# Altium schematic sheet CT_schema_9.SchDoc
size 274 x 160 mm
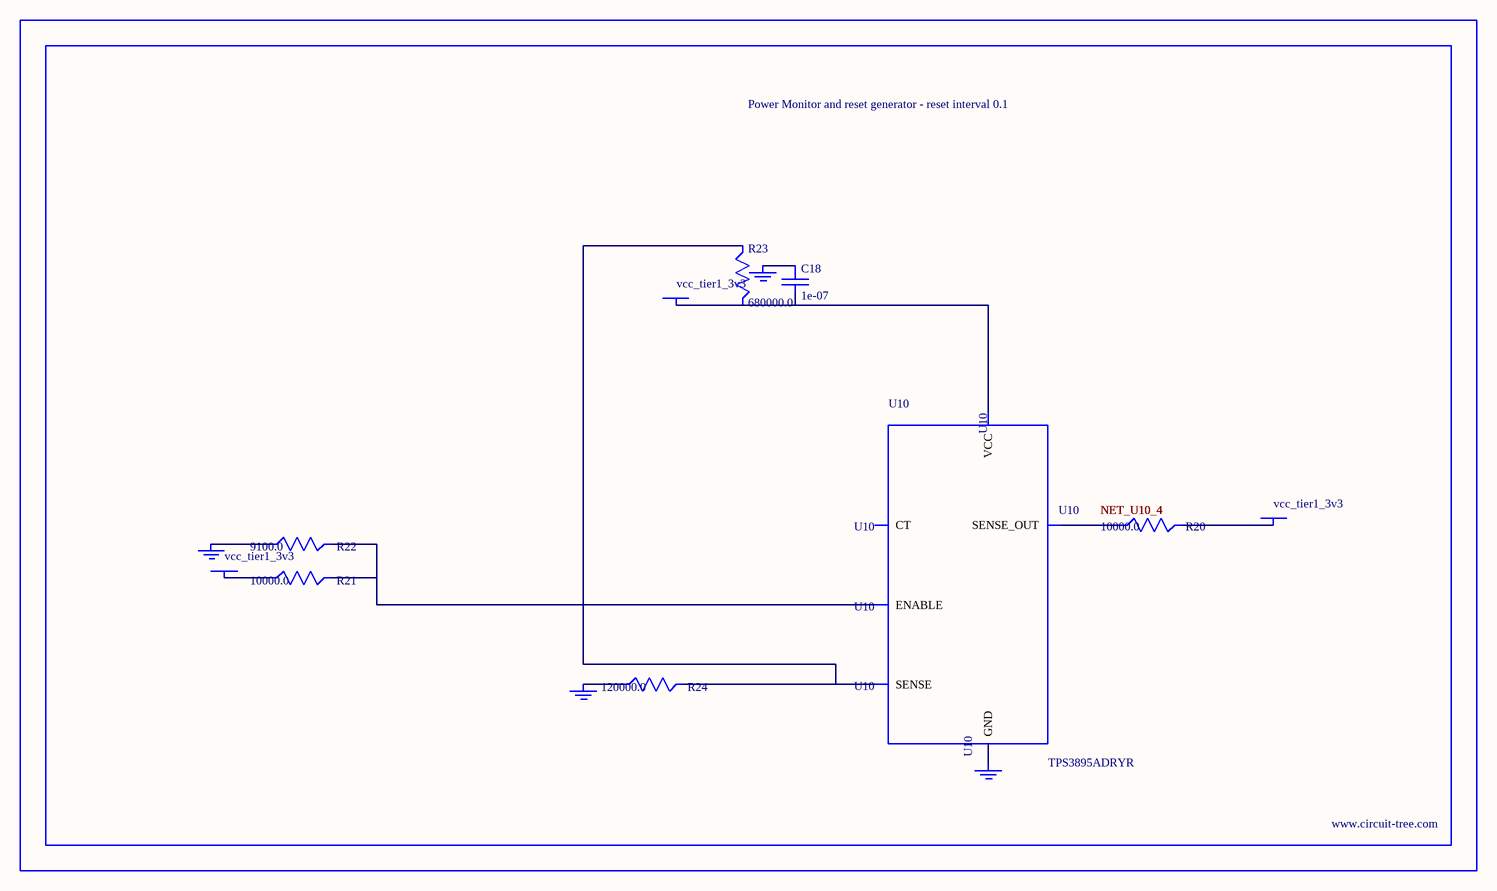
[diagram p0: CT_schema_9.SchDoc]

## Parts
BORDER8  (no value)
C18  1e-07  [C0402]
GND_INSTANCE_8_0  (no value)
GND_INSTANCE_8_1  (no value)
GND_INSTANCE_8_2  (no value)
GND_INSTANCE_8_3  (no value)
POWER_INSTANCE_8_0  vcc_tier1_3v3
POWER_INSTANCE_8_1  vcc_tier1_3v3
POWER_INSTANCE_8_2  vcc_tier1_3v3
R20  10000.0  [R0603]
R21  10000.0  [R0603]
R22  9100.0  [R0603]
R23  680000.0  [R0603]
R24  120000.0  [R0603]
U10  TPS3895ADRYR  [SON-6]

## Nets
NetC18_1: C18.1 GND_INSTANCE_8_2.0(GND)
NetC18_2: C18.2 POWER_INSTANCE_8_2.0(PWR) R23.2 U10.6(VCC)
NetGND_INSTANCE_8_0_0: GND_INSTANCE_8_0.0(GND) R22.1
NetGND_INSTANCE_8_1_0: GND_INSTANCE_8_1.0(GND) R24.1
NetGND_INSTANCE_8_3_0: GND_INSTANCE_8_3.0(GND) U10.2(GND)
NetPOWER_INSTANCE_8_0_0: POWER_INSTANCE_8_0.0(PWR) R21.1
NetPOWER_INSTANCE_8_1_0: POWER_INSTANCE_8_1.0(PWR) R20.2
NetR20_1: R20.1 U10.4(SENSE_OUT)
NetR21_2: R21.2 R22.2 U10.1(ENABLE)
NetR23_1: R23.1 R24.2 U10.3(SENSE)

Not connected (* = marked no-connect by the designer): U10 5(CT)

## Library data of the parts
BORDER8 = BORDER_PAGE8
C18 = C0402C104K3RACTU
GND_INSTANCE_8_0-GND_INSTANCE_8_3 = GND
POWER_INSTANCE_8_0-POWER_INSTANCE_8_2 = PWR
R20 R21 = RC0603JR-0710KL
R22 = RC0603JR-079K1L
R23 = RC0603JR-07680KL
R24 = RC0603JR-07120KL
